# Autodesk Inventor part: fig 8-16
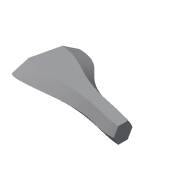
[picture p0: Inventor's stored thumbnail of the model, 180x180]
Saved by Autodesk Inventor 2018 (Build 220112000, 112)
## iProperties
Created: 2004-05
Part Number: fig 8-16
Document SubType Name: Modeling
Designer: CADCIM Technologies
Manufacturer: Standard
Standards Organization: Custom
Density: 1 g/cm^3
Material: Generic
Appearance: Default
Author: CADCIM Technologies
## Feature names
1. Sweep7
## Parameters: d6 = 0, d7 = 0
